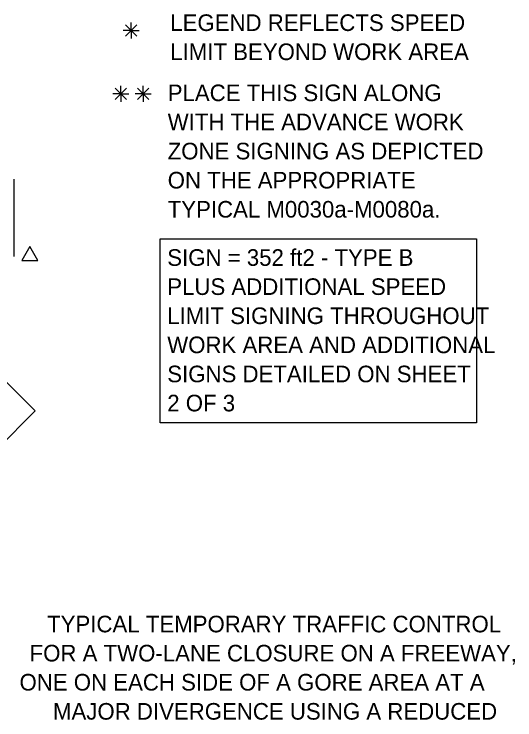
# Model space of a CAD drawing. Extents: x 16512 to 19504, y 5761 to 6984.
# Drawn here: x 17156.7 to 17437.2, y 5988.2 to 6383.4 of the extents above; entities that cross this region are included whole.
import ezdxf

# ---------------------------------------------------------------- set-up
doc = ezdxf.new("R2010")
doc.units = 0
for name, color, linetype in [('BORDER', 7, 'Continuous'), ('TRAFFIC_SIGNS_PR', 7, 'Continuous'), ('TYPICAL_TEXT_DIMEN_EX', 7, 'Continuous'), ('TYPICAL_TEXT_DIMEN_PR', 7, 'Continuous')]:
    doc.layers.add(name, color=color, linetype=linetype)

msp = doc.modelspace()

# ---------------------------------------------------------------- linework, layer by layer
at = {"layer": 'BORDER'}
msp.add_line((17289.25, 6011.25), (17289.25, 6011.25), dxfattribs=at)
msp.add_line((17289.25, 6011.25), (17289.25, 6011.25), dxfattribs=at)
at = {"layer": 'TRAFFIC_SIGNS_PR'}
for p, q in [((17156.74, 6247.73), (17156.74, 6290.93)), ((17168.51, 6161.16), (17141.36, 6188.31)), ((17141.36, 6134.01), (17168.51, 6161.16))]:
    msp.add_line(p, q, dxfattribs=at)
at = {"layer": 'TYPICAL_TEXT_DIMEN_EX'}
msp.add_lwpolyline([(17238.46, 6257.51), (17415.73, 6257.51), (17415.73, 6154.47), (17238.46, 6154.47)], close=True, dxfattribs=at)
at = {"layer": 'TYPICAL_TEXT_DIMEN_PR'}
for p, q in [((17219.11, 6377.43), (17225.48, 6371.05)), ((17225.48, 6377.43), (17219.11, 6371.05)), ((17222.3, 6374.24), (17222.3, 6378.7)), ((17222.3, 6374.24), (17217.76, 6374.24)), ((17222.3, 6374.24), (17225.48, 6374.24)), ((17222.3, 6374.24), (17226.77, 6374.24)), ((17222.3, 6374.24), (17222.3, 6369.74)), ((17213.28, 6341.93), (17219.66, 6335.55)), ((17219.66, 6341.93), (17213.28, 6335.55)), ((17216.47, 6338.74), (17216.47, 6343.19)), ((17225.84, 6341.93), (17232.21, 6335.55)), ((17232.21, 6341.93), (17225.84, 6335.55)), ((17229.02, 6338.74), (17229.02, 6343.19)), ((17216.47, 6338.74), (17211.94, 6338.74)), ((17216.47, 6338.74), (17219.66, 6338.74)), ((17216.47, 6338.74), (17220.95, 6338.74)), ((17216.47, 6338.74), (17216.47, 6334.24)), ((17229.02, 6338.74), (17224.49, 6338.74)), ((17229.02, 6338.74), (17232.21, 6338.74)), ((17229.02, 6338.74), (17233.5, 6338.74)), ((17229.02, 6338.74), (17229.02, 6334.24))]:
    msp.add_line(p, q, dxfattribs=at)
msp.add_lwpolyline([(17165.5, 6253.3), (17160.98, 6245.46), (17170.03, 6245.46)], close=True, dxfattribs=at)

# ---------------------------------------------------------------- texts
at = {"layer": 'BORDER'}
for s, p in [('TYPICAL TEMPORARY TRAFFIC CONTROL', (17175.21, 6037.21)), ('FOR A TWO-LANE CLOSURE ON A FREEWAY,', (17165.41, 6020.91)), ('ONE ON EACH SIDE OF A GORE AREA AT A ', (17159.75, 6004.62)), ('MAJOR DIVERGENCE USING A REDUCED', (17178.52, 5988.32))]:
    msp.add_text(s, height=9.3, dxfattribs=at).set_placement(p)
at = {"layer": 'TYPICAL_TEXT_DIMEN_EX'}
for s, p in [('LEGEND REFLECTS SPEED', (17244.2, 6373.97)), ('LIMIT BEYOND WORK AREA', (17244.2, 6357.67)), ('PLACE THIS SIGN ALONG', (17242.76, 6334.67)), ('WITH THE ADVANCE WORK', (17242.76, 6318.37)), ('ZONE SIGNING AS DEPICTED', (17242.76, 6302.07)), ('ON THE APPROPRIATE', (17242.76, 6285.77)), ('TYPICAL M0030a-M0080a.', (17242.76, 6269.47)), ('SIGN = 352 ft2 - TYPE B', (17242.51, 6242.45)), ('PLUS ADDITIONAL SPEED', (17242.51, 6226.15)), ('LIMIT SIGNING THROUGHOUT', (17242.51, 6209.85)), ('WORK AREA AND ADDITIONAL', (17242.51, 6193.55)), ('SIGNS DETAILED ON SHEET', (17242.51, 6177.25)), ('2 OF 3', (17242.51, 6160.95))]:
    msp.add_text(s, height=9.3, dxfattribs=at).set_placement(p)

doc.saveas('drawing.dxf')
